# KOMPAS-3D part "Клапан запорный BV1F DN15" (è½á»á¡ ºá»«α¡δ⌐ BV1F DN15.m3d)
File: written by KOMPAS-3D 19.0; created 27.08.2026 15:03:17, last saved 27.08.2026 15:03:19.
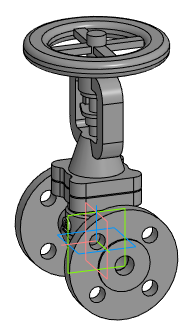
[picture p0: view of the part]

Document properties: Автор: Энергия; Полное имя файла: E:\Dendor\_3D для проектировщиков\5.6 Клапан запорный BV1F\stp\Клапан запорный BV1F DN15.m3d

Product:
- Part/product: Клапан запорный BV1F DN15
    Масса: 4.3008

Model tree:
1. Операция без истории:1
